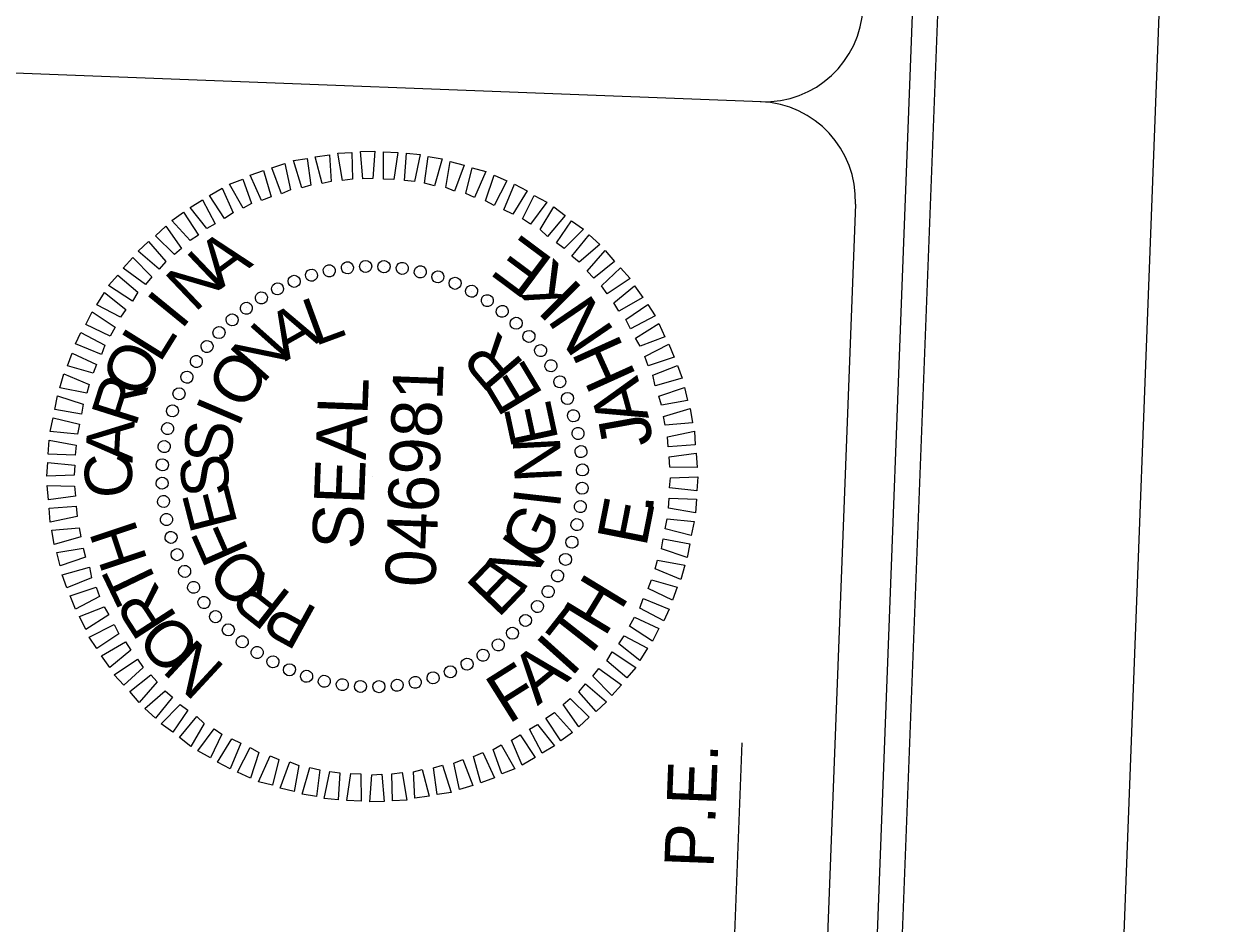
# Model space of a CAD drawing. Extents: x 2094564 to 2100382, y 679033 to 692366.
# Drawn here: x 2099771 to 2100382, y 689098 to 689554 of the extents above; entities that cross this region are included whole.
import ezdxf

# ---------------------------------------------------------------- set-up
doc = ezdxf.new("R2010")
doc.units = 0
for name, color, linetype in [('Prop Horizontal Alignment Direction Label', 7, 'Continuous'), ('Prop Horizontal Alignment Tick Label', 7, 'Continuous'), ('Prop Horizontal Alignment Tick Large', 7, 'Continuous'), ('Sheet PE Seal Cell', 7, 'Continuous')]:
    doc.layers.add(name, color=color, linetype=linetype)

msp = doc.modelspace()

# ---------------------------------------------------------------- linework, layer by layer
at = {"layer": 'Prop Horizontal Alignment Direction Label'}
for p, q in [((2100144.8, 689514.58), (2099345.38, 689545.23)), ((2100107.97, 688482.63), (2100135.15, 689189.6))]:
    msp.add_line(p, q, dxfattribs=at)
for points in [[(2099968.83, 682967.66), (2100252.42, 690362.22)], [(2100154.56, 688464.58), (2100192.84, 689462.72)]]:
    msp.add_lwpolyline(points, dxfattribs=at)
for centre, start, end in [((2100146.43, 689564.57), 267.8037, 357.8037), ((2100142.59, 689464.64), 357.8037, 87.8037)]:
    msp.add_arc(centre, 50, start, end, dxfattribs=at)
at = {"layer": 'Prop Horizontal Alignment Tick Label'}
msp.add_lwpolyline([(2099950.14, 682147.77), (2100269.47, 690474.15), (2094997.85, 690676.32), (2094678.52, 682349.95)], close=True, dxfattribs=at)
at = {"layer": 'Prop Horizontal Alignment Tick Large'}
msp.add_lwpolyline([(2094886.54, 690703.11), (2094563.86, 682289.3), (2100059.76, 682078.52), (2100382.44, 690492.33)], close=True, dxfattribs=at)
at = {"layer": 'Sheet PE Seal Cell'}
for p, q in [((2099925.68, 689428.98), (2099925.68, 689428.98)), ((2099935.08, 689430.32), (2099935.08, 689430.32)), ((2099944.26, 689431.25), (2099944.26, 689431.25)), ((2099953.61, 689431.1), (2099953.61, 689431.1)), ((2099962.93, 689430.1), (2099962.93, 689430.1)), ((2099908.04, 689423.7), (2099908.04, 689423.7)), ((2099916.66, 689426.77), (2099916.66, 689426.77)), ((2099972.01, 689428.27), (2099972.01, 689428.27)), ((2099980.85, 689426.01), (2099980.85, 689426.01)), ((2099989.66, 689422.7), (2099989.66, 689422.7)), ((2099899.59, 689419.77), (2099899.59, 689419.77)), ((2099998, 689418.55), (2099998, 689418.55)), ((2099891.33, 689415.2), (2099891.33, 689415.2)), ((2100006.12, 689413.99), (2100006.12, 689413.99)), ((2099883.7, 689410.18), (2099883.7, 689410.18)), ((2100013.56, 689408.39), (2100013.56, 689408.39)), ((2099876.45, 689404.07), (2099876.45, 689404.07)), ((2100020.78, 689402.37), (2100020.78, 689402.37)), ((2099869.82, 689397.74), (2099869.82, 689397.74)), ((2100027.11, 689395.74), (2100027.11, 689395.74)), ((2099863.81, 689390.52), (2099863.81, 689390.52)), ((2100033.22, 689388.49), (2100033.22, 689388.49)), ((2099858.2, 689383.08), (2099858.2, 689383.08)), ((2100038.24, 689380.86), (2100038.24, 689380.86)), ((2099853.64, 689374.96), (2099853.64, 689374.96)), ((2100042.81, 689372.6), (2100042.81, 689372.6)), ((2099849.49, 689366.62), (2099849.49, 689366.62)), ((2100046.74, 689364.16), (2100046.74, 689364.16)), ((2099846.18, 689357.81), (2099846.18, 689357.81)), ((2100049.81, 689355.53), (2100049.81, 689355.53)), ((2099843.92, 689348.97), (2099843.92, 689348.97)), ((2100052.02, 689346.52), (2100052.02, 689346.52)), ((2099842.09, 689339.89), (2099842.09, 689339.89)), ((2100053.36, 689337.11), (2100053.36, 689337.11)), ((2099841.09, 689330.58), (2099841.09, 689330.58)), ((2100054.28, 689327.93), (2100054.28, 689327.93)), ((2099840.95, 689321.22), (2099840.95, 689321.22)), ((2099947.62, 689324.58), (2099947.62, 689324.58)), ((2100054.14, 689318.58), (2100054.14, 689318.58)), ((2099841.87, 689312.04), (2099841.87, 689312.04)), ((2100053.14, 689309.26), (2100053.14, 689309.26)), ((2099843.21, 689302.64), (2099843.21, 689302.64)), ((2100051.31, 689300.18), (2100051.31, 689300.18)), ((2099845.42, 689293.62), (2099845.42, 689293.62)), ((2100049.05, 689291.34), (2100049.05, 689291.34)), ((2099848.49, 689285), (2099848.49, 689285)), ((2100045.74, 689282.53), (2100045.74, 689282.53)), ((2099852.42, 689276.55), (2099852.42, 689276.55)), ((2100041.59, 689274.19), (2100041.59, 689274.19)), ((2099856.99, 689268.3), (2099856.99, 689268.3)), ((2100037.03, 689266.07), (2100037.03, 689266.07)), ((2099862.02, 689260.66), (2099862.02, 689260.66)), ((2100031.42, 689258.63), (2100031.42, 689258.63)), ((2099868.12, 689253.41), (2099868.12, 689253.41)), ((2099874.46, 689246.79), (2099874.46, 689246.79)), ((2100025.41, 689251.42), (2100025.41, 689251.42)), ((2099881.67, 689240.77), (2099881.67, 689240.77)), ((2100018.78, 689245.08), (2100018.78, 689245.08)), ((2099889.11, 689235.17), (2099889.11, 689235.17)), ((2100003.9, 689233.95), (2100003.9, 689233.95)), ((2100011.53, 689238.98), (2100011.53, 689238.98)), ((2099897.23, 689230.6), (2099897.23, 689230.6)), ((2099995.64, 689229.38), (2099995.64, 689229.38)), ((2099905.57, 689226.45), (2099905.57, 689226.45)), ((2099914.38, 689223.14), (2099914.38, 689223.14)), ((2099978.57, 689222.38), (2099978.57, 689222.38)), ((2099987.2, 689225.45), (2099987.2, 689225.45)), ((2099923.22, 689220.88), (2099923.22, 689220.88)), ((2099932.3, 689219.05), (2099932.3, 689219.05)), ((2099941.62, 689218.05), (2099941.62, 689218.05)), ((2099950.97, 689217.91), (2099950.97, 689217.91)), ((2099960.15, 689218.83), (2099960.15, 689218.83)), ((2099969.56, 689220.17), (2099969.56, 689220.17))]:
    msp.add_line(p, q, dxfattribs=at)
for points in [[(2099911.97, 689470.97), (2099907.61, 689484.75), (2099914.67, 689485.76), (2099916.49, 689472.29)], [(2099922.26, 689473.13), (2099918.74, 689486.66), (2099926.01, 689487.66), (2099926.77, 689474.23)], [(2099932.53, 689474.65), (2099930.09, 689488.57), (2099937.33, 689488.93), (2099937.66, 689475.31)], [(2099942.77, 689475.54), (2099941.6, 689489.4), (2099948.84, 689489.55), (2099947.88, 689475.76)], [(2099953.4, 689475.34), (2099953.29, 689489.17), (2099960.51, 689488.89), (2099958.49, 689475.14)], [(2099964.01, 689474.72), (2099964.96, 689488.51), (2099971.95, 689487.81), (2099969.09, 689474.1)], [(2099974.16, 689473.27), (2099975.95, 689486.81), (2099983.14, 689485.68), (2099979.21, 689472.01)], [(2099984.92, 689471.15), (2099987.13, 689484.25), (2099994.29, 689482.49), (2099989.32, 689469.28)], [(2099891.52, 689464.53), (2099885.64, 689477.3), (2099892.54, 689479.8), (2099896.28, 689466.47)], [(2099901.65, 689467.97), (2099896.63, 689481.13), (2099903.3, 689483.22), (2099906.19, 689469.92)], [(2099995.01, 689468), (2099998.27, 689481.06), (2100005.22, 689479.31), (2099999.4, 689466.13)], [(2099882.23, 689460.63), (2099875.26, 689472.81), (2099881.94, 689475.32), (2099886.36, 689463.03)], [(2100005.08, 689464.43), (2100009.41, 689477.45), (2100015.88, 689474.43), (2100009.45, 689461.92)], [(2100014.26, 689459.82), (2100019.65, 689472.8), (2100026.11, 689469.36), (2100018.85, 689457.52)], [(2099872.68, 689455.47), (2099865.04, 689467.03), (2099871.56, 689470.82), (2099877.04, 689458.28)], [(2100023.86, 689455.2), (2100029.64, 689467.1), (2100036.1, 689463.66), (2100027.8, 689452.5)], [(2099863.76, 689450.28), (2099855.24, 689461.03), (2099861.55, 689464.83), (2099867.89, 689452.68)], [(2100032.8, 689449.75), (2100039.63, 689461.4), (2100045.41, 689456.93), (2100036.49, 689446.21)], [(2099855.23, 689444.23), (2099846.05, 689454.36), (2099851.96, 689458.6), (2099859.59, 689447.04)], [(2100041.05, 689443.06), (2100048.71, 689454.25), (2100054.71, 689449.98), (2100044.98, 689440.14)], [(2099847.3, 689437.09), (2099837.67, 689446.6), (2099842.97, 689451.5), (2099850.82, 689440.15)], [(2100048.87, 689436.38), (2100057.58, 689447.1), (2100062.92, 689442.22), (2100052.58, 689433.26)], [(2099839.58, 689429.73), (2099828.87, 689438.86), (2099834.16, 689443.76), (2099842.92, 689433.64)], [(2099832.69, 689421.91), (2099821.31, 689430.22), (2099826.19, 689435.56), (2099835.81, 689425.84)], [(2100056.66, 689428.64), (2100065.78, 689439.13), (2100070.46, 689433.64), (2100059.93, 689425.11)], [(2100063.82, 689421.34), (2100073.52, 689430.33), (2100078.42, 689425.04), (2100066.64, 689417.2)], [(2099825.98, 689413.45), (2099813.95, 689421.36), (2099818.62, 689426.71), (2099828.71, 689418.03)], [(2099819.93, 689405.39), (2099808.05, 689411.59), (2099811.9, 689417.82), (2099822.63, 689409.33)], [(2100070.08, 689412.6), (2100080.62, 689421.34), (2100084.86, 689415.43), (2100072.68, 689408.46)], [(2100076.14, 689404.28), (2100087.27, 689411.73), (2100091.09, 689406.05), (2100078.51, 689399.51)], [(2099814.67, 689395.81), (2099802.35, 689401.6), (2099805.57, 689408.07), (2099817.19, 689400.39)], [(2100081.09, 689394.74), (2100092.86, 689402.15), (2100096, 689395.44), (2100083.48, 689390.61)], [(2099810.27, 689386.41), (2099797.08, 689391.81), (2099799.86, 689397.65), (2099811.95, 689391.24)], [(2099806.08, 689377), (2099793.04, 689380.69), (2099795.42, 689387.19), (2099807.74, 689381.4)], [(2100085.84, 689385.41), (2100097.99, 689391.75), (2100100.71, 689385.05), (2100087.57, 689380.67)], [(2100089.94, 689375.9), (2100102.46, 689380.95), (2100104.77, 689374.48), (2100091.01, 689370.54)], [(2099802.93, 689366.91), (2099789.21, 689369.57), (2099791.19, 689376.72), (2099804.16, 689371.33)], [(2100092.94, 689365.36), (2100105.86, 689369.76), (2100107.52, 689363.1), (2100094.25, 689360.85)], [(2099800.18, 689356.17), (2099786.66, 689358.61), (2099787.99, 689365.57), (2099801.01, 689361.25)], [(2100095.3, 689355.06), (2100108.85, 689359.01), (2100110.06, 689351.73), (2100096.2, 689350.56)], [(2099798.09, 689346.05), (2099784.32, 689347.43), (2099785.86, 689354.38), (2099799.14, 689351.11)], [(2100097.25, 689344.78), (2100110.97, 689347.66), (2100111.34, 689340.63), (2100097.69, 689339.66)], [(2099797.05, 689335.45), (2099783.24, 689335.98), (2099783.73, 689342.98), (2099797.45, 689340.54)], [(2099796.44, 689325.27), (2099782.6, 689324.74), (2099783.08, 689331.74), (2099796.85, 689330.36)], [(2100098.13, 689334.54), (2100111.81, 689336.35), (2100112.38, 689329.1), (2100098.57, 689329.42)], [(2099797.1, 689314.61), (2099783.42, 689312.8), (2099782.85, 689320.05), (2099796.66, 689319.73)], [(2100098.79, 689323.88), (2100112.63, 689324.41), (2100112.15, 689317.42), (2100098.38, 689318.79)], [(2100098.18, 689313.7), (2100111.99, 689313.17), (2100111.51, 689306.17), (2100097.78, 689308.61)], [(2099797.98, 689304.37), (2099784.26, 689301.49), (2099783.89, 689308.53), (2099797.54, 689309.49)], [(2100097.14, 689303.11), (2100110.91, 689301.73), (2100109.37, 689294.77), (2100096.09, 689298.04)], [(2099799.93, 689294.09), (2099786.38, 689290.14), (2099785.17, 689297.42), (2099799.04, 689298.59)], [(2099802.3, 689283.79), (2099789.37, 689279.39), (2099787.71, 689286.05), (2099800.98, 689288.31)], [(2100095.05, 689292.98), (2100108.57, 689290.55), (2100107.24, 689283.58), (2100094.22, 689287.91)], [(2100092.3, 689282.24), (2100106.02, 689279.58), (2100104.04, 689272.43), (2100091.07, 689277.82)], [(2099805.29, 689273.26), (2099792.77, 689268.21), (2099790.46, 689274.67), (2099804.22, 689278.61)], [(2100089.15, 689272.15), (2100102.19, 689268.46), (2100099.81, 689261.96), (2100087.49, 689267.75)], [(2099809.39, 689263.74), (2099797.24, 689257.4), (2099794.52, 689264.1), (2099807.66, 689268.49)], [(2099814.14, 689254.41), (2099802.37, 689247), (2099799.23, 689253.71), (2099811.75, 689258.55)], [(2100084.96, 689262.74), (2100098.15, 689257.35), (2100095.37, 689251.5), (2100083.29, 689257.92)], [(2100080.56, 689253.34), (2100092.88, 689247.55), (2100089.66, 689241.08), (2100078.04, 689248.76)], [(2099819.09, 689244.87), (2099807.96, 689237.43), (2099804.14, 689243.1), (2099816.72, 689249.64)], [(2099825.15, 689236.55), (2099814.61, 689227.81), (2099810.37, 689233.72), (2099822.55, 689240.7)], [(2100075.3, 689243.76), (2100087.18, 689237.56), (2100083.33, 689231.33), (2100072.6, 689239.82)], [(2100069.25, 689235.7), (2100081.28, 689227.8), (2100076.61, 689222.45), (2100066.52, 689231.13)], [(2099831.41, 689227.81), (2099821.71, 689218.82), (2099816.81, 689224.12), (2099828.59, 689231.96)], [(2100062.54, 689227.24), (2100073.92, 689218.93), (2100069.04, 689213.59), (2100059.42, 689223.32)], [(2099838.57, 689220.52), (2099829.45, 689210.02), (2099824.77, 689215.52), (2099835.3, 689224.04)], [(2099846.36, 689212.77), (2099837.65, 689202.05), (2099832.31, 689206.93), (2099842.65, 689215.89)], [(2100055.65, 689219.42), (2100066.36, 689210.29), (2100061.07, 689205.39), (2100052.31, 689215.51)], [(2099854.18, 689206.09), (2099846.52, 689194.91), (2099840.52, 689199.18), (2099850.25, 689209.01)], [(2100047.93, 689212.06), (2100057.56, 689202.55), (2100052.27, 689197.65), (2100044.41, 689209.01)], [(2099862.43, 689199.4), (2099855.6, 689187.75), (2099849.82, 689192.23), (2099858.74, 689202.94)], [(2100040, 689204.92), (2100049.18, 689194.79), (2100043.27, 689190.55), (2100035.64, 689202.11)], [(2099871.37, 689193.95), (2099865.59, 689182.05), (2099859.13, 689185.49), (2099867.43, 689196.66)], [(2100031.47, 689198.87), (2100039.99, 689188.12), (2100033.68, 689184.32), (2100027.34, 689196.48)], [(2099880.97, 689189.33), (2099875.58, 689176.35), (2099869.12, 689179.79), (2099876.38, 689191.63)], [(2100022.55, 689193.68), (2100030.19, 689182.12), (2100023.67, 689178.33), (2100018.19, 689190.87)], [(2099890.15, 689184.73), (2099885.82, 689171.71), (2099879.35, 689174.72), (2099885.78, 689187.23)], [(2100003.71, 689184.62), (2100009.6, 689171.85), (2100002.69, 689169.35), (2099998.95, 689182.68)], [(2100013, 689188.52), (2100019.98, 689176.34), (2100013.29, 689173.84), (2100008.87, 689186.13)], [(2099900.22, 689181.15), (2099896.96, 689168.09), (2099890.01, 689169.85), (2099895.83, 689183.02)], [(2099910.31, 689178), (2099908.1, 689164.9), (2099900.94, 689166.66), (2099905.91, 689179.87)], [(2099983.26, 689178.18), (2099987.62, 689164.4), (2099980.56, 689163.4), (2099978.74, 689176.86)], [(2099993.58, 689181.18), (2099998.6, 689168.02), (2099991.93, 689165.94), (2099989.04, 689179.23)], [(2099921.07, 689175.88), (2099919.28, 689162.34), (2099912.09, 689163.47), (2099916.02, 689177.14)], [(2099931.22, 689174.43), (2099930.27, 689160.65), (2099923.28, 689161.34), (2099926.14, 689175.05)], [(2099941.83, 689173.81), (2099941.94, 689159.99), (2099934.72, 689160.26), (2099936.74, 689174.01)], [(2099952.46, 689173.62), (2099953.63, 689159.75), (2099946.39, 689159.6), (2099947.35, 689173.39)], [(2099962.7, 689174.5), (2099965.14, 689160.58), (2099957.9, 689160.22), (2099957.57, 689173.85)], [(2099972.97, 689176.02), (2099976.49, 689162.49), (2099969.22, 689161.49), (2099968.46, 689174.92)]]:
    msp.add_lwpolyline(points, close=True, dxfattribs=at)
for centre, major_axis in [((2099916.8, 689426.61), (-0.88, 2.93)), ((2099925.81, 689428.91), (-0.63, 3)), ((2099934.99, 689430.42), (-0.36, 3.04)), ((2099944.26, 689431.11), (-0.1, 3.06)), ((2099953.56, 689431), (0.17, 3.06)), ((2099962.81, 689430.08), (0.44, 3.03)), ((2099971.95, 689428.35), (0.7, 2.98)), ((2099980.9, 689425.84), (0.96, 2.91)), ((2099899.55, 689419.71), (-1.38, 2.73)), ((2099908.02, 689423.54), (-1.14, 2.84)), ((2099989.6, 689422.55), (1.21, 2.81)), ((2099891.44, 689415.16), (-1.61, 2.6)), ((2099997.98, 689418.52), (1.45, 2.7)), ((2100005.97, 689413.77), (1.68, 2.56)), ((2099883.76, 689409.92), (-1.83, 2.45)), ((2100013.53, 689408.34), (1.89, 2.4)), ((2099876.56, 689404.03), (-2.04, 2.28)), ((2100020.58, 689402.28), (2.09, 2.23)), ((2099869.91, 689397.54), (-2.23, 2.09)), ((2100027.07, 689395.63), (2.28, 2.04)), ((2099863.85, 689390.49), (-2.4, 1.89)), ((2099858.42, 689382.94), (-2.56, 1.68)), ((2100032.96, 689388.43), (2.45, 1.83)), ((2100038.2, 689380.75), (2.6, 1.61)), ((2099853.67, 689374.94), (-2.7, 1.45)), ((2100042.75, 689372.64), (2.73, 1.38)), ((2099849.64, 689366.56), (-2.81, 1.21)), ((2100046.58, 689364.17), (2.84, 1.14)), ((2099846.36, 689357.86), (-2.91, 0.96)), ((2100049.65, 689355.39), (2.93, 0.88)), ((2099843.84, 689348.91), (-2.98, 0.7)), ((2100051.95, 689346.38), (3, 0.63)), ((2099842.11, 689339.77), (-3.03, 0.44)), ((2100053.45, 689337.2), (3.04, 0.36)), ((2099841.19, 689330.52), (-3.06, 0.17)), ((2100054.15, 689327.93), (3.06, 0.1)), ((2099841.08, 689321.22), (-3.06, -0.1)), ((2100054.04, 689318.63), (3.06, -0.17)), ((2099841.78, 689311.95), (-3.04, -0.36)), ((2100053.12, 689309.38), (3.03, -0.44)), ((2099843.28, 689302.77), (-3, -0.63)), ((2100051.39, 689300.24), (2.98, -0.7)), ((2099845.58, 689293.76), (-2.93, -0.88)), ((2100048.87, 689291.29), (2.91, -0.96)), ((2099848.65, 689284.99), (-2.84, -1.14)), ((2100045.59, 689282.59), (2.81, -1.21)), ((2099852.48, 689276.51), (-2.73, -1.38)), ((2100041.56, 689274.21), (2.7, -1.45)), ((2099857.03, 689268.4), (-2.6, -1.61)), ((2099862.27, 689260.72), (-2.45, -1.83)), ((2100036.81, 689266.22), (2.56, -1.68)), ((2100031.38, 689258.67), (2.4, -1.89)), ((2099868.16, 689253.53), (-2.28, -2.04)), ((2100025.32, 689251.62), (2.23, -2.09)), ((2099874.65, 689246.87), (-2.09, -2.23)), ((2100018.67, 689245.12), (2.04, -2.28)), ((2099881.7, 689240.81), (-1.89, -2.4)), ((2100011.47, 689239.23), (1.83, -2.45)), ((2099889.26, 689235.38), (-1.68, -2.56)), ((2099897.25, 689230.63), (-1.45, -2.7)), ((2100003.79, 689233.99), (1.61, -2.6)), ((2099905.63, 689226.6), (-1.21, -2.81)), ((2099987.21, 689225.61), (1.14, -2.84)), ((2099995.68, 689229.44), (1.38, -2.73)), ((2099914.33, 689223.32), (-0.96, -2.91)), ((2099923.28, 689220.8), (-0.7, -2.98)), ((2099932.42, 689219.07), (-0.44, -3.03)), ((2099941.67, 689218.15), (-0.17, -3.06)), ((2099950.97, 689218.04), (0.1, -3.06)), ((2099960.24, 689218.74), (0.36, -3.04)), ((2099969.42, 689220.24), (0.63, -3)), ((2099978.43, 689222.54), (0.88, -2.93))]:
    msp.add_ellipse(centre, major_axis=major_axis, ratio=0.999708, dxfattribs=at)

# ---------------------------------------------------------------- texts
at = {"layer": 'Prop Horizontal Alignment Direction Label'}
msp.add_text('P.E.', height=24.997, rotation=87.8037, dxfattribs=at).set_placement((2100120.63, 689125.86))
at = {"layer": 'Sheet PE Seal Cell'}
for s, height, rotation, p in [('A', 23.96, 36.42085, (2099870.65, 689419.4)), ('E', 25.49, 143.29672, (2100040.25, 689434.17)), ('N', 23.96, 43.62261, (2099857.65, 689407.35)), ('K', 25.49, 135.0128, (2100055.07, 689419.68)), ('I', 23.96, 50.82384, (2099850.71, 689398.47)), ('L', 23.97, 20.20455, (2099918.46, 689390.55)), ('N', 25.49, 124.28697, (2100070.89, 689398.02)), ('A', 23.97, 29.56397, (2099903.49, 689382.83)), ('L', 23.96, 58.02457, (2099839.86, 689381.66)), ('N', 23.96, 48.28031, (2099891.98, 689371.15)), ('R', 23.96, 130.28511, (2100025.29, 689381.57)), ('H', 25.49, 114.30299, (2100081.76, 689375.53)), ('O', 23.96, 65.22486, (2099831.29, 689363.28)), ('O', 23.96, 57.63718, (2099882.95, 689357.25)), ('046981', 25.492, 87.8037, (2099979.51, 689268.18)), ('E', 23.96, 120.92779, (2100034.7, 689366.11)), ('R', 23.96, 72.4248, (2099827.56, 689349.17)), ('A', 25.49, 105.46268, (2100088, 689354.31)), ('SEAL', 25.492, 87.8037, (2099942.58, 689287.35)), ('I', 23.96, 66.9933, (2099879.65, 689348.87)), ('E', 23.96, 102.21546, (2100042.11, 689343.28)), ('A', 23.96, 86.82402, (2099826.02, 689331.37)), ('S', 23.96, 85.7041, (2099875.97, 689330.73)), ('J', 25.49, 100.20486, (2100090.13, 689341.32)), ('N', 23.96, 92.86009, (2100043.86, 689322.16)), ('C', 23.96, 94.02357, (2099826.65, 689314.54)), ('S', 23.96, 95.05931, (2099875.6, 689315.43)), ('E', 23.96, 104.41477, (2099879.5, 689300.61)), ('I', 23.96, 83.5049, (2100042.67, 689307.96)), ('E', 25.49, 78.86139, (2100086.45, 689288.3)), ('G', 23.96, 64.79394, (2100033.54, 689280.45)), ('.', 25.49, 85.97073, (2100089.87, 689305.76)), ('H', 23.96, 108.42318, (2099833.91, 689281.94)), ('F', 23.96, 113.77073, (2099885.35, 689286.77)), ('N', 23.96, 55.43766, (2100023.36, 689264.68)), ('O', 23.96, 132.48494, (2099897.34, 689272.28)), ('E', 23.96, 46.08059, (2100011.41, 689252.38)), ('T', 23.96, 115.62347, (2099840.39, 689267.87)), ('R', 23.97, 141.84335, (2099907.46, 689264.45)), ('R', 23.96, 122.82421, (2099849.18, 689253.07)), ('H', 25.49, 58.67705, (2100065.41, 689242.63)), ('P', 23.97, 151.20259, (2099920.79, 689257.13)), ('T', 25.49, 51.87681, (2100054.88, 689229.25)), ('O', 23.96, 130.02544, (2099861.78, 689237.91)), ('N', 23.96, 137.2272, (2099873.72, 689227.67)), ('I', 25.49, 48.07486, (2100048.32, 689222.35)), ('A', 25.49, 39.23455, (2100031.41, 689208.09)), ('F', 25.49, 32.21794, (2100016.56, 689198.73))]:
    msp.add_text(s, height=height, rotation=rotation, dxfattribs=at).set_placement(p)

doc.saveas('drawing.dxf')
